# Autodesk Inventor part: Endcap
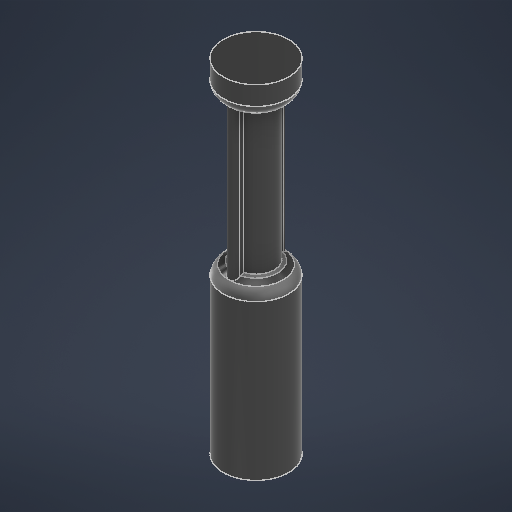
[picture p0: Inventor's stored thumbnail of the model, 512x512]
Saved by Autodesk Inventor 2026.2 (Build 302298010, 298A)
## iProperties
Created: 2026-05
Part Number: Endcap
Material: PBT 플라스틱
Document SubType Name: Modeling
Designer: work
Density: 1.31 g/cm^3
Appearance: 섬세 텍스처 - 검은색
Author: work
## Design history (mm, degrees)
sketch "스케치1"
  geometry: C1 r 3 at (0, 0); 1 further point
  constraints: 1 centre point, 1 coincident
  dimensions: "d0" = 6 diameter of C1
extrude "돌출1" new body sketch "스케치1" distance "d1" = 31.5; taper "d2" = 0 deg
sketch "스케치2"
  geometry: C1 r 1.5 at (0, 0); 1 further point
  constraints: 1 centre point, 1 coincident
  dimensions: "d3" = 3 diameter of C1
extrude "돌출2" cut sketch "스케치2" distance "d4" = 12; taper "d5" = 0 deg
node "작업 평면1"
sketch "스케치3"
  geometry: L1 (-0.5, -2.5)-(0.5, -2.5); L2 (0.5, -2.5)-(0.5, 2.5); L3 (0.5, 2.5)-(-0.5, 2.5); L4 (-0.5, 2.5)-(-0.5, -2.5); L5 (-0.5, -2.5)-(0.5, 2.5); L6 (0.5, -2.5)-(-0.5, 2.5); C1 r 1.7 at (0, 0); C2 r 1.5 at (0, 0) reference; C3 r 3 at (0, 0) reference; 5 further points
  constraints: 12 end point, 2 midpoint, 2 parallel, 1 centre point, 1 coincident, 1 horizontal, 1 perpendicular
  dimensions: "d7" = 3.4 diameter of C1; "d10" = 1 distance of L3.end L2.end; "d11" = 5 distance of L2.end L1.end
extrude "돌출3" cut sketch "스케치3" distance "d8" = 13; taper "d9" = 0 deg
fillet "모깎기1" dims "d12" = 0.5
chamfer "모따기1" distance "d13" = 1.2; stored, may be unused: second distance "d14" = 2, angle "d15" = 30 deg
chamfer "모따기2" distance "d16" = 1.2; stored, may be unused: second distance "d17" = 2, angle "d18" = 30 deg
fillet "모깎기2" dims "d19" = 1
node "솔리드1"
node "투영된 루프1"
other parameters: "d6" = -3
